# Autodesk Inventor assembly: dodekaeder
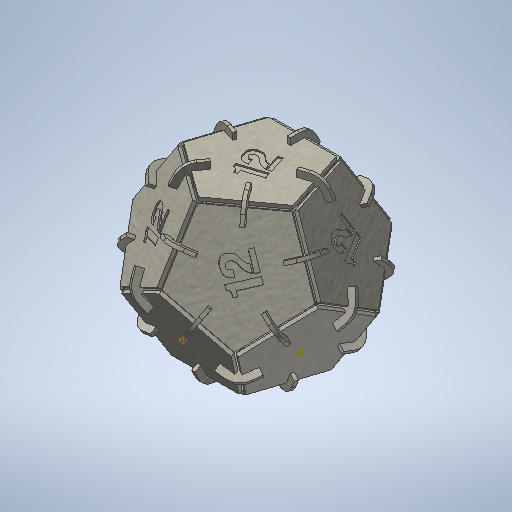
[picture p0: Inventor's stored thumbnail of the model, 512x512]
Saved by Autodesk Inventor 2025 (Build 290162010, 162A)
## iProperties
Created: 2025-02
Part Number: dodekaeder
Material: Generisch
Document SubType Name: Assembly
Designer: BennF
Author: BennF
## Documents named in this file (3)
- C:\Users\BennF\OneDrive - Technische Universität Ilmenau\FabAcademy\week03\dodecahedron.iam
- C:\Users\BennF\OneDrive - Technische Universität Ilmenau\FabAcademy\week03\pentagon_tile.ipt
- C:\Users\BennF\OneDrive - Technische Universität Ilmenau\FabAcademy\week03\conector_116.ipt
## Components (42 placed, 2 different names)
1. pentagon_tile:1 — Mate:1, Mate:2, Mate:3
2. pentagon_tile:12 — Mate:25, Mate:26, Mate:27
3. conector_116:1 — Mate:1, Mate:2, Mate:3, Mate:4, Mate:5, Mate:6
4. pentagon_tile:2 — Mate:4, Mate:5, Mate:6, Mate:7, Mate:8, Mate:9, Mate:10, Mate:11, Mate:12
5. conector_116:2 — Mate:7, Mate:8, Mate:9
6. conector_116:3
7. pentagon_tile:3
8. conector_116:4
9. conector_116:5
10. pentagon_tile:4
11. conector_116:6
12. conector_116:7
13. pentagon_tile:5
14. conector_116:8
15. conector_116:9
16. pentagon_tile:6 — Mate:13, Mate:14, Mate:15
17. conector_116:10
18. conector_116:11 — Mate:10, Mate:11, Mate:12, Mate:16, Mate:17, Mate:18
19. conector_116:12 — Mate:13, Mate:14, Mate:15
20. pentagon_tile:7
21. conector_116:13 — Mate:19, Mate:20, Mate:21
22. conector_116:14 — Mate:22, Mate:23, Mate:24
23. conector_116:15
24. conector_116:16
25. pentagon_tile:8
26. conector_116:17
27. conector_116:18 — Mate:25, Mate:26, Mate:27
28. conector_116:19
29. conector_116:20
30. pentagon_tile:9
31. conector_116:21
32. conector_116:22
33. conector_116:23
34. conector_116:24
35. pentagon_tile:10
36. conector_116:25
37. conector_116:26
38. conector_116:27
39. conector_116:28
40. pentagon_tile:11
41. conector_116:29
42. conector_116:30
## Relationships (27: Mate 27)
- Mate:1: pentagon_tile:1 ↔ conector_116:1
- Mate:2: pentagon_tile:1 ↔ conector_116:1
- Mate:3: pentagon_tile:1 ↔ conector_116:1
- Mate:4: conector_116:1 ↔ pentagon_tile:2
- Mate:5: conector_116:1 ↔ pentagon_tile:2
- Mate:6: conector_116:1 ↔ pentagon_tile:2
- Mate:7: pentagon_tile:2 ↔ conector_116:2
- Mate:8: pentagon_tile:2 ↔ conector_116:2
- Mate:9: pentagon_tile:2 ↔ conector_116:2
- Mate:10: pentagon_tile:2 ↔ conector_116:11
- Mate:11: pentagon_tile:2 ↔ conector_116:11
- Mate:12: pentagon_tile:2 ↔ conector_116:11
- Mate:13: pentagon_tile:6 ↔ conector_116:12
- Mate:14: pentagon_tile:6 ↔ conector_116:12
- Mate:15: pentagon_tile:6 ↔ conector_116:12
- Mate:16: conector_116:11
- Mate:17: conector_116:11
- Mate:18: conector_116:11
- Mate:19: conector_116:13
- Mate:20: conector_116:13
- Mate:21: conector_116:13
- Mate:22: conector_116:14
- Mate:23: conector_116:14
- Mate:24: conector_116:14
- Mate:25: pentagon_tile:12 ↔ conector_116:18
- Mate:26: pentagon_tile:12 ↔ conector_116:18
- Mate:27: pentagon_tile:12 ↔ conector_116:18
